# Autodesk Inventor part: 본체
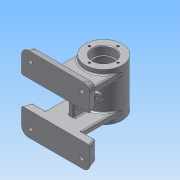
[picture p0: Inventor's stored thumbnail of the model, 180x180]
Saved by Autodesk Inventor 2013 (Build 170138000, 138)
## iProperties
Created: 2016-07
Part Number: 본체
Material: 알루미늄 6061
Document SubType Name: Modeling
Designer: Administrator
Density: 2.71 g/cm^3
Mass: 498.632 g
Surface Area: 541.48 cm^2
Volume: 183.997 cm^3
Author: Administrator
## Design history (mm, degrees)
sketch "스케치1"
  geometry: C1 r 27 at (0, 0); 1 further point
  constraints: 1 centre point, 1 coincident
  dimensions: "d0" = 54 diameter of C1
extrude "돌출1" new body sketch "스케치1" stored distance "d1" = 70; taper "d2" = 0 deg
sketch "스케치2"
  geometry: C1 r 27 at (0, 0) reference; C2 r 16 at (0, 0)
  constraints: 1 centre point, 1 coincident
  dimensions: "d3" = 32 diameter of C2
extrude "돌출2" cut sketch "스케치2" distance "d4" = 12; taper "d5" = 0 deg
sketch "스케치3"
  geometry: C1 r 16 at (0, 0) reference; C2 r 14 at (0, 0)
  constraints: 1 centre point, 1 coincident
  dimensions: "d6" = 28 diameter of C2
extrude "돌출3" cut sketch "스케치3" distance "d7" = 2; taper "d8" = 0 deg
sketch "스케치4"
  geometry: C1 r 14 at (0, 0) reference; C2 r 22 at (0, 0)
  constraints: 1 centre point, 1 coincident
  dimensions: "d9" = 44 diameter of C2
extrude "돌출4" cut sketch "스케치4" distance "d10" = 42; taper "d11" = 0 deg
sketch "스케치5"
  geometry: C1 r 27 at (0, 0) reference; C2 r 16 at (0, 0)
  constraints: 1 centre point, 1 coincident
  dimensions: "d12" = 32 diameter of C2
extrude "돌출5" cut sketch "스케치5" distance "d13" = 12; taper "d14" = 0 deg
sketch "스케치6"
  geometry: C1 r 16 at (0, 0) reference; C2 r 14 at (0, 0)
  constraints: 1 centre point, 1 coincident
  dimensions: "d15" = 28 diameter of C2
extrude "돌출6" cut sketch "스케치6" distance "d16" = 2; taper "d17" = 0 deg
node "작업 평면3"
sketch "스케치11"
  geometry: L1 (50, 20)-(-50, 20); L2 (-50, 20)-(-50, 55); L3 (-50, 55)-(50, 55); L4 (50, 55)-(50, 20); L5 (50, 20)-(-50, 55); L6 (-50, 20)-(50, 55); 3 further points
  constraints: 12 end point, 3 midpoint, 2 parallel, 1 horizontal, 1 perpendicular, 1 vertical alignment
  dimensions: "d27" = 100 distance of L2.end L3.end; "d29" = 35 distance of L1.end L2.end; "d30" = 55 distance from line of L3 point (0, 0)
extrude "돌출8" join sketch "스케치11" distance "d31" = 12; taper "d32" = 0 deg
fillet "모깎기2" dims "d33" = 10
feature "면 기울기1" dims angle "d34" = 20 deg
sketch "스케치12"
  geometry: L1 (-45.632, -45)-(-45.632, -20) reference; L2 (-45.632, -20)-(45.632, -20) reference; L3 (45.632, -20)-(45.632, -45) reference; L4 (40, -50.632)-(-40, -50.632) reference; L5 (-50, -45)-(-50, -20) reference; L6 (40, -55)-(-40, -55) reference; L7 (50, -20)-(50, -45) reference; A1 r 5.632 centre (-40, -45) between (-45.632, -45) and (-40, -50.632) reference; A2 r 5.632 centre (40, -45) between (40, -50.632) and (45.632, -45) reference; 3 further points
  dimensions: "d35" = 12.5 distance from line of L5 point (-37.5, -42.5); "d36" = 12.5 distance from line of point (-37.5, -42.5) L6; "d37" = 12.5 distance from line of L7 point (37.5, -42.5); "d38" = 12.5 distance from line of point (37.5, -42.5) L6
hole "구멍1" sketch "스케치12" at (-37.5, -42.5), (37.5, -42.5) diameter "d39" = 6; stored, may be unused: countersink angle "d43" = 90 deg, drill point angle "d45" = 0 deg; dims "d40" = 6, "d41" = 10, "d42" = 4, "d44" = 8
fillet "모깎기3" dims "d46" = 2
sketch "스케치13"
  geometry: L1 (44.232, -20)-(-44.232, -20) reference; L2 (27, -28)-(-27, -28); L3 (-27, -28)-(-27, -20); L4 (-27, -20)-(27, -20); L5 (27, -20)-(27, -28); L6 (27, -28)-(-27, -20); L7 (-27, -28)-(27, -20); 3 further points
  constraints: 12 end point, 3 midpoint, 2 parallel, 1 horizontal, 1 perpendicular, 1 point on line, 1 vertical alignment
  dimensions: "d47" = 8 distance of L2.end L3.end; "d48" = 54 distance of L3.end L4.end
extrude "돌출9" join sketch "스케치13" stored distance "d49" = 12; taper "d50" = 0 deg
node "작업 평면4"
sketch "스케치15"
  geometry: L1 (4, -25)-(-4, -25); L2 (-4, -25)-(-4, 25); L3 (-4, 25)-(4, 25); L4 (4, 25)-(4, -25); L5 (4, -25)-(-4, 25); L6 (-4, -25)-(4, 25); 2 further points
  constraints: 12 end point, 2 midpoint, 2 parallel, 1 coincident, 1 horizontal, 1 perpendicular
  dimensions: "d55" = 8 distance of L2.end L3.end; "d57" = 50 distance of L1.end L2.end
extrude "돌출10" join sketch "스케치15" distance "d58" = 22; taper "d59" = 0 deg
sketch "스케치16"
  geometry: L1 (40, 0)-(0, 0) reference; L2 (12, 13.5)-(28, 13.5); L3 (12, 6.5)-(28, 6.5); L4 (55, 63.492)-(43, 63.492) reference; L5 (43, 63.492)-(43, 61.416) reference; L6 (43, 61.416)-(41, 61.416) reference; L7 (41, 61.416)-(41, 69.633) reference; L8 (41, 69.633)-(-1, 69.633) reference; L9 (-1, 69.633)-(-1, 61.416) reference; L10 (-1, 61.416)-(-3, 61.416) reference; L11 (-3, 61.416)-(-3, 63.492) reference; L12 (-3, 63.492)-(-15, 63.492) reference; L13 (-15, 63.492)-(-15, 74.702) reference; L14 (-15, 74.702)-(55, 74.702) reference; L15 (55, 74.702)-(55, 63.492) reference; L16 (71.111, -11.316)-(75, -22) reference; L17 (75, -22)-(40, -22) reference; L18 (40, -22)-(40, 0) reference; L19 (40, 0)-(0, 0) reference; L20 (0, 21.298)-(0, 0) reference; L21 (48, -10)-(69.232, -10) reference; L22 (48, 21.298)-(48, -10) reference; L23 (55, 21.298)-(48, 21.298) reference; L24 (55, 32.508)-(55, 21.298) reference; L25 (43, 32.508)-(55, 32.508) reference; L26 (43, 34.584)-(43, 32.508) reference; L27 (41, 34.584)-(43, 34.584) reference; L28 (41, 26.367)-(41, 34.584) reference; L29 (-1, 26.367)-(41, 26.367) reference; L30 (-1, 34.584)-(-1, 26.367) reference; L31 (-3, 34.584)-(-1, 34.584) reference; L32 (-3, 32.508)-(-3, 34.584) reference; L33 (-15, 32.508)-(-3, 32.508) reference; L34 (-15, 21.298)-(-15, 32.508) reference; L35 (-8, 21.298)-(-15, 21.298) reference; L36 (-8, -10)-(-8, 21.298) reference; L37 (-29.232, -10)-(-8, -10) reference; L38 (-35, -22)-(-31.111, -11.316) reference; L39 (0, -22)-(-35, -22) reference; L40 (0, 0)-(0, -22) reference; L41 (40, 0)-(40, 21.298) reference; L42 (20, 13.5)-(20, 6.5); L43 (40, 21.298)-(0, 21.298) reference; A1 r 3.5 centre (28, 10) between (28, 6.5) and (28, 13.5); A2 r 3.5 centre (12, 10) between (12, 13.5) and (12, 6.5); A3 r 2 centre (69.232, -12) between (71.111, -11.316) and (69.232, -10) reference; A4 r 2 centre (-29.232, -12) between (-29.232, -10) and (-31.111, -11.316) reference; 1 further point
  constraints: 6 end point, 4 point on circle, 3 parallel, 3 tangent, 2 centre point, 2 midpoint
  dimensions: "d60" = 3.5 radius of A1; "d61" = 3.5 radius of A2; "d62" = 23 dimension on A1 A2; "d63" = 32 distance from line of L17 A1.centre; "d64" = 35 distance between parallel lines of L42 L13; "d65" = 8 distance from line of L42 A2.centre
extrude "돌출11" cut sketch "스케치16" stored distance "d66" = 12; taper "d67" = 0 deg
fillet "모깎기4" dims "d68" = 2
node "작업 평면6"
sketch "스케치17"
  geometry: L1 (-27, -35)-(27, -35) reference; C1 r 5 at (0, -13); 1 further point
  constraints: 1 centre point, 1 vertical alignment
  dimensions: "d71" = 5 radius of C1; "d73" = 22 distance from line of C1.centre L1
extrude "돌출12" join sketch "스케치17" stored distance "d74" = 12; taper "d75" = 0 deg
hole "구멍2" diameter "d78" = 5.188; stored, may be unused: countersink angle "d82" = 90 deg, drill point angle "d84" = 0 deg; dims "d79" = 13, "d80" = 10, "d81" = 4, "d83" = 15, "d109" = 10, "d110" = 10
node "작업 평면7"
sketch "스케치18"
  geometry: L1 (-27, -35)-(27, -35) reference; L2 (58, -49.232)-(58, -28) reference; L3 (58, -28)-(0, -28) reference; L4 (0, -28)-(0, -20) reference; L5 (0, -20)-(0, 20) reference; L6 (0, 20)-(0, 28) reference; L7 (0, 28)-(0, 35) reference; L8 (70, -55)-(59.316, -51.111) reference; L9 (70, -20)-(70, -55) reference; L10 (58, -20)-(70, -20) reference; L11 (0, -20)-(58, -20) reference; L12 (58, -28)-(58, -20) reference; L13 (0, -35)-(0, -28) reference; L14 (58, 20)-(0, 20) reference; L15 (70, 20)-(58, 20) reference; L16 (70, 55)-(70, 20) reference; L17 (59.316, 51.111)-(70, 55) reference; L18 (58, 28)-(58, 49.232) reference; L19 (0, 28)-(58, 28) reference; L20 (58, 20)-(58, 28) reference; A1 r 2 centre (60, -49.232) between (58, -49.232) and (59.316, -51.111) reference; A2 r 2 centre (60, 49.232) between (59.316, 51.111) and (58, 49.232) reference; 2 further points
  constraints: 1 other
  dimensions: "d85" = 35 distance from line of L1 point (0, 0); "d86" = 27 horizontal distance of point (0, 0) L1.start
feature "엠보싱1" sketch "스케치18" dims "d0" = 54, "d87" = 0.5, "d88" = 0
sketch "스케치19"
  geometry: L1 (0, 0)-(11.601, -20.093); L2 (0, 0)-(0, -24.439); L3 (15, -25.981)-(9.804, -28.981); L4 (9.804, -28.981)-(6.405, -23.093); L5 (6.405, -23.093)-(11.601, -20.093); L6 (11.601, -20.093)-(15, -25.981); L7 (11.601, -20.093)-(15, -25.981)
  constraints: 14 end point, 3 perpendicular, 2 parallel, 1 vertical
  dimensions: "d89" = 30 distance of L1.start L3.start; "d90" = 30 deg angle of L1 L2; "d91" = 6 distance of L3.start L3.end; "d92" = 5.88746 vertical distance of L3.end L4.end
revolve "회전1" sketch "스케치19" stored, may be unused: angle "d93" = 90 deg
hole "구멍3" diameter "d96" = 5.188; stored, may be unused: countersink angle "d100" = 90 deg, drill point angle "d102" = 0 deg; dims "d94" = 10, "d95" = 10, "d97" = 10, "d98" = 10, "d99" = 4, "d101" = 8
fillet "모깎기5" dims "d103" = 0.3, "d104" = 2
chamfer "모따기1" distance "d105" = 1; stored, may be unused: second distance "d106" = 2, angle "d107" = 45 deg
fillet "모깎기6" dims "d108" = 2
fillet "모깎기7" dims "d111" = 2
sketch "스케치20"
  geometry: C1 r 27 at (0, 0) reference; 1 further point
  constraints: 1 vertical alignment
  dimensions: "d112" = 21 distance of C1.centre point (0, 21)
sketch "스케치21"
  geometry: C1 r 27 at (0, 0) reference; 1 further point
  constraints: 1 vertical alignment
  dimensions: "d113" = 21 distance of point (0, 21) C1.centre
hole "구멍4" sketch "스케치21" at (0, 21) diameter "d114" = 3.242; stored, may be unused: countersink angle "d118" = 90 deg, drill point angle "d120" = 118 deg; dims "d115" = 8, "d116" = 10, "d117" = 4, "d119" = 10
hole "구멍5" sketch "스케치20" diameter "d121" = 3.242; stored, may be unused: countersink angle "d125" = 90 deg, drill point angle "d127" = 118 deg; dims "d122" = 8, "d123" = 10, "d124" = 4, "d126" = 10
fillet "모깎기8" dims "d131" = 2
node "솔리드1"
mirror "대칭1"
pattern_circular "원형 패턴1" dims angle "d129" = 360 deg
node "절단 모서리 투영1"
node "절단 모서리 투영2"
node "절단 모서리 투영3"
other parameters: "d54" = -48
